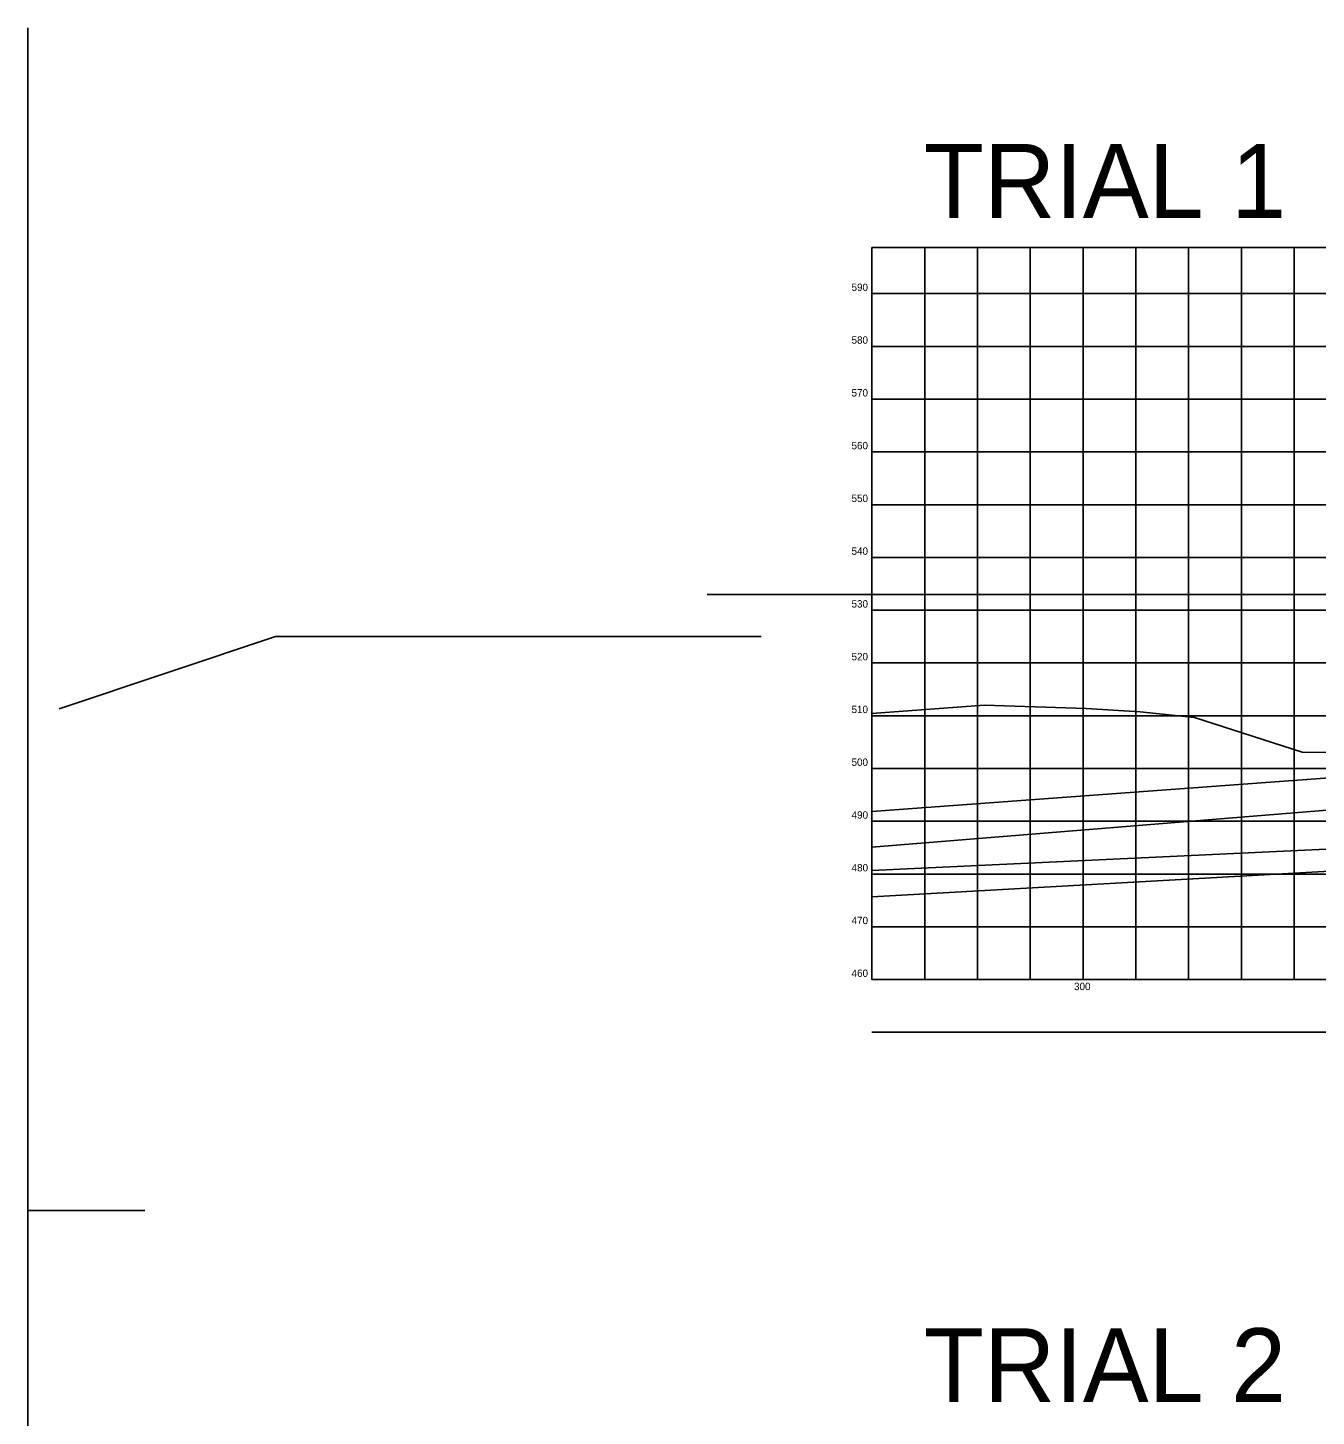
# Model space of a CAD drawing. Extents: x -64 to 1064, y -32 to 640.
# Drawn here: x 500 to 744.2, y 377.2 to 640.4 of the extents above; entities that cross this region are included whole.
import ezdxf

# ---------------------------------------------------------------- set-up
doc = ezdxf.new("R2010")
doc.units = 0
for name, color, linetype in [('DR_X_Trench_Drain', 7, 'Continuous'), ('GT_Project_Soil_Layers', 7, 'Continuous'), ('PV_X_Text', 7, 'Continuous'), ('SC_Scratch1', 7, 'Continuous'), ('SH_Major_Grid_Line', 7, 'Continuous'), ('SH_Text', 7, 'Continuous')]:
    doc.layers.add(name, color=color, linetype=linetype)

msp = doc.modelspace()

# ---------------------------------------------------------------- linework, layer by layer
at = {"layer": 'DR_X_Trench_Drain'}
for p, q in [((500, 640.38), (500, 416.26)), ((500, 416.26), (500, 192.14))]:
    msp.add_line(p, q, dxfattribs=at)
at = {"layer": 'GT_Project_Soil_Layers'}
for p, q in [((660, 491.84), (880, 508)), ((660, 485.1), (880, 503)), ((660, 480.69), (880, 491)), ((660, 475.69), (880, 488)), ((500, 416.26), (522.18, 416.26))]:
    msp.add_line(p, q, dxfattribs=at)
at = {"layer": 'PV_X_Text'}
for p, q in [((505.92, 511.32), (546.96, 525)), ((546.96, 525), (638.98, 525))]:
    msp.add_line(p, q, dxfattribs=at)
at = {"layer": 'SC_Scratch1'}
msp.add_line((909.57, 533), (628.77, 533), dxfattribs=at)
msp.add_lwpolyline([(751.61, 503.01), (741.55, 503.07), (721.15, 509.66), (710.8, 510.72), (700.56, 511.4), (681.26, 512), (660, 510.45)], dxfattribs=at)
at = {"layer": 'SH_Major_Grid_Line'}
for p, q in [((1060, 598.71), (660, 598.71)), ((660, 460), (660, 598.71)), ((670, 460), (670, 598.71)), ((680, 460), (680, 598.71)), ((690, 460), (690, 598.71)), ((700, 460), (700, 598.71)), ((710, 460), (710, 598.71)), ((720, 460), (720, 598.71)), ((730, 460), (730, 598.71)), ((740, 460), (740, 598.71)), ((1060, 590), (660, 590)), ((1060, 580), (660, 580)), ((1060, 570), (660, 570)), ((1060, 560), (660, 560)), ((1060, 550), (660, 550)), ((1060, 540), (660, 540)), ((1060, 530), (660, 530)), ((1060, 520), (660, 520)), ((1060, 510), (660, 510)), ((1060, 500), (660, 500)), ((1060, 490), (660, 490)), ((1060, 480), (660, 480)), ((1060, 470), (660, 470)), ((1060, 460), (660, 460)), ((1060, 450), (660, 450))]:
    msp.add_line(p, q, dxfattribs=at)

# ---------------------------------------------------------------- texts
at = {"layer": 'GT_Project_Soil_Layers'}
for s, p in [('TRIAL 1', (669.8, 604.36)), ('TRIAL 2', (669.8, 379.91))]:
    msp.add_text(s, height=14, dxfattribs=at).set_placement(p)
at = {"layer": 'SH_Text'}
for s, p in [('590', (656.12, 590.5)), ('580', (656.12, 580.5)), ('570', (656.12, 570.5)), ('560', (656.12, 560.5)), ('550', (656.12, 550.5)), ('540', (656.12, 540.5)), ('530', (656.12, 530.5)), ('520', (656.12, 520.5)), ('510', (656.12, 510.5)), ('500', (656.12, 500.5)), ('490', (656.13, 490.5)), ('480', (656.13, 480.5)), ('470', (656.13, 470.5)), ('460', (656.13, 460.5)), ('300', (698.29, 458))]:
    msp.add_text(s, height=1.4, dxfattribs=at).set_placement(p)

doc.saveas('drawing.dxf')
